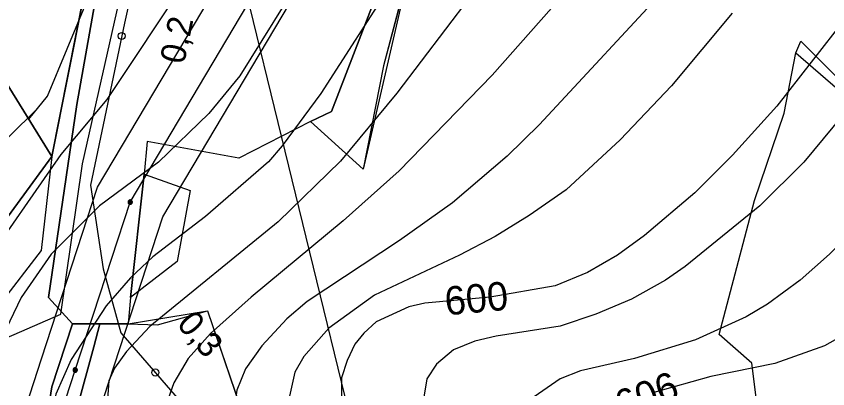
# Model space of a CAD drawing. Extents: x -709418 to -703832, y -1161719 to -1157826.
# Drawn here: x -706899.8 to -706671.8, y -1159381.5 to -1159276.9 of the extents above; entities that cross this region are included whole.
import ezdxf

# ---------------------------------------------------------------- set-up
doc = ezdxf.new("R2010")
doc.units = 0
for name, color, linetype in [('102_obvod PÚ', 7, 'Continuous'), ('106_zastavitelné plochy', 7, 'Continuous'), ('120_vrstevnice hlavní', 7, 'Continuous'), ('121_vrstevnice hlavní_popis', 7, 'Continuous'), ('122_vrstevnice základní', 7, 'Continuous'), ('206_TTP_KN', 7, 'Continuous'), ('207_lesní pozemek_KN', 7, 'Continuous'), ('210_ostatní plocha_KN', 7, 'Continuous'), ('301_polní cesta_stav', 7, 'Continuous'), ('705_el VN nadzemní_E.ON', 7, 'Continuous'), ('723_radioreléová trasa_UAP', 7, 'Continuous'), ('735_OP sítí TI', 7, 'Continuous'), ('Trasa-Hlavni  staniceni', 7, 'Continuous')]:
    doc.layers.add(name, color=color, linetype=linetype)

# ---------------------------------------------------------------- blocks, each defined once
blk = doc.blocks.new('Elektro - Implicitní$0$VN4601')
for points in [[(1.23, 0), (1.22, 0.13), (1.2, 0.26), (1.17, 0.38), (1.12, 0.5), (1.06, 0.61), (0.99, 0.72), (0.91, 0.82), (0.82, 0.91), (0.72, 0.99), (0.61, 1.06), (0.5, 1.12), (0.38, 1.17), (0.26, 1.2), (0.13, 1.22), (0, 1.23), (-0.13, 1.22), (-0.26, 1.2), (-0.38, 1.17), (-0.5, 1.12), (-0.61, 1.06), (-0.72, 0.99), (-0.82, 0.91), (-0.91, 0.82), (-0.99, 0.72), (-1.06, 0.61), (-1.12, 0.5), (-1.17, 0.38), (-1.2, 0.26), (-1.22, 0.13), (-1.23, 0), (-1.22, -0.13), (-1.2, -0.26), (-1.17, -0.38), (-1.12, -0.5), (-1.06, -0.61), (-0.99, -0.72), (-0.91, -0.82), (-0.82, -0.91), (-0.72, -0.99), (-0.61, -1.06), (-0.5, -1.12), (-0.38, -1.17), (-0.26, -1.2), (-0.13, -1.22), (0, -1.23), (0.13, -1.22), (0.26, -1.2), (0.38, -1.17), (0.5, -1.12), (0.61, -1.06), (0.72, -0.99), (0.82, -0.91), (0.91, -0.82), (0.99, -0.72), (1.06, -0.61), (1.12, -0.5), (1.17, -0.38), (1.2, -0.26), (1.22, -0.13), (1.23, 0)], [(0.92, 0), (0.92, 0.1), (0.9, 0.19), (0.88, 0.28), (0.84, 0.37), (0.8, 0.46), (0.75, 0.54), (0.68, 0.62), (0.62, 0.68), (0.54, 0.74), (0.46, 0.8), (0.37, 0.84), (0.28, 0.88), (0.19, 0.9), (0.1, 0.92), (0, 0.92), (-0.1, 0.92), (-0.19, 0.9), (-0.28, 0.88), (-0.37, 0.84), (-0.46, 0.8), (-0.54, 0.74), (-0.62, 0.68), (-0.68, 0.62), (-0.75, 0.54), (-0.8, 0.46), (-0.84, 0.37), (-0.88, 0.28), (-0.9, 0.19), (-0.92, 0.1), (-0.92, 0), (-0.92, -0.1), (-0.9, -0.19), (-0.88, -0.29), (-0.84, -0.38), (-0.8, -0.46), (-0.75, -0.54), (-0.68, -0.62), (-0.62, -0.69), (-0.54, -0.75), (-0.46, -0.8), (-0.37, -0.84), (-0.28, -0.88), (-0.19, -0.9), (-0.1, -0.92), (0, -0.92), (0.1, -0.92), (0.19, -0.9), (0.28, -0.88), (0.37, -0.84), (0.46, -0.8), (0.54, -0.75), (0.62, -0.69), (0.68, -0.62), (0.75, -0.54), (0.8, -0.46), (0.84, -0.38), (0.88, -0.29), (0.9, -0.19), (0.92, -0.1), (0.92, 0)], [(0.61, 0), (0.61, 0.06), (0.6, 0.13), (0.58, 0.19), (0.56, 0.25), (0.53, 0.31), (0.5, 0.36), (0.46, 0.41), (0.41, 0.46), (0.36, 0.5), (0.31, 0.53), (0.25, 0.56), (0.19, 0.58), (0.13, 0.6), (0.06, 0.61), (0, 0.61), (-0.06, 0.61), (-0.13, 0.6), (-0.19, 0.58), (-0.25, 0.56), (-0.31, 0.53), (-0.36, 0.5), (-0.41, 0.46), (-0.46, 0.41), (-0.5, 0.36), (-0.53, 0.31), (-0.56, 0.25), (-0.58, 0.19), (-0.6, 0.13), (-0.61, 0.06), (-0.61, 0), (-0.61, -0.07), (-0.6, -0.13), (-0.58, -0.19), (-0.56, -0.25), (-0.53, -0.31), (-0.5, -0.36), (-0.46, -0.41), (-0.41, -0.46), (-0.36, -0.5), (-0.31, -0.53), (-0.25, -0.56), (-0.19, -0.58), (-0.13, -0.6), (-0.06, -0.61), (0, -0.61), (0.06, -0.61), (0.13, -0.6), (0.19, -0.58), (0.25, -0.56), (0.31, -0.53), (0.36, -0.5), (0.41, -0.46), (0.46, -0.41), (0.5, -0.36), (0.53, -0.31), (0.56, -0.25), (0.58, -0.19), (0.6, -0.13), (0.61, -0.06), (0.61, 0)], [(0.31, 0), (0.31, 0.03), (0.3, 0.06), (0.29, 0.09), (0.28, 0.12), (0.27, 0.15), (0.25, 0.18), (0.23, 0.21), (0.21, 0.23), (0.18, 0.25), (0.15, 0.27), (0.12, 0.28), (0.09, 0.29), (0.06, 0.3), (0.03, 0.31), (0, 0.31), (-0.03, 0.31), (-0.06, 0.3), (-0.09, 0.29), (-0.12, 0.28), (-0.15, 0.27), (-0.18, 0.25), (-0.21, 0.23), (-0.23, 0.21), (-0.25, 0.18), (-0.27, 0.15), (-0.28, 0.12), (-0.29, 0.09), (-0.3, 0.06), (-0.31, 0.03), (-0.31, 0), (-0.31, -0.03), (-0.3, -0.06), (-0.29, -0.1), (-0.28, -0.13), (-0.27, -0.15), (-0.25, -0.18), (-0.23, -0.21), (-0.21, -0.23), (-0.18, -0.25), (-0.15, -0.27), (-0.12, -0.28), (-0.09, -0.29), (-0.06, -0.3), (-0.03, -0.31), (0, -0.31), (0.03, -0.31), (0.06, -0.3), (0.09, -0.29), (0.12, -0.28), (0.15, -0.27), (0.18, -0.25), (0.21, -0.23), (0.23, -0.21), (0.25, -0.18), (0.27, -0.15), (0.28, -0.13), (0.29, -0.1), (0.3, -0.06), (0.31, -0.03), (0.31, 0)]]:
    blk.add_lwpolyline(points)
blk = doc.blocks.new('_kolecko-HB')
blk.add_circle((0, 0), 0.5)

msp = doc.modelspace()

# ---------------------------------------------------------------- linework, layer by layer
at = {"layer": '102_obvod PÚ'}
for points in [[(-706968.04, -1159233.11), (-706937.28, -1159184.2), (-706914.8, -1159202.04), (-706906.78, -1159204.53), (-706877.16, -1159210.67), (-706869.31, -1159212.81), (-706889.81, -1159316.26), (-706920.66, -1159266.5), (-706951.63, -1159256.73), (-706968.04, -1159233.11)], [(-706968.04, -1159233.11), (-706951.63, -1159256.73), (-706920.66, -1159266.5), (-706889.81, -1159316.26), (-706869.31, -1159212.81), (-706877.16, -1159210.67), (-706906.78, -1159204.53), (-706914.8, -1159202.04), (-706937.28, -1159184.2), (-706968.04, -1159233.11)], [(-706788.31, -1159259.5), (-706796.68, -1159290.77), (-706802.33, -1159319.86), (-706817.16, -1159306.4), (-706837.26, -1159316.76), (-706863.04, -1159312.08), (-706863.88, -1159321.25), (-706850.99, -1159325.84), (-706854.62, -1159345.77), (-706867.73, -1159355.84), (-706868.36, -1159363.26), (-706860.13, -1159363.56), (-706846.05, -1159359.62), (-706835.89, -1159389.45)], [(-706689.26, -1159404.94), (-706693.14, -1159374.31), (-706702.27, -1159366.26), (-706692.33, -1159328.63), (-706684.03, -1159304.11), (-706680.78, -1159287.17), (-706679.32, -1159283.86), (-706646.77, -1159316.53)]]:
    msp.add_lwpolyline(points, dxfattribs=at)
at = {"layer": '106_zastavitelné plochy'}
for points in [[(-706867.98, -1159123.82), (-706903.51, -1159148.06), (-706940.53, -1159172.06), (-706937.28, -1159184.2), (-706968.04, -1159233.11), (-706951.63, -1159256.73), (-706920.66, -1159266.5), (-706889.81, -1159316.26), (-706892.83, -1159342.7), (-706904.42, -1159357.69), (-706932.38, -1159369.27), (-706950.1, -1159377.45), (-706984.19, -1159324.98), (-706993.05, -1159311.35), (-707005.32, -1159252.75), (-706918.72, -1159056.21)], [(-706984.14, -1159571.11), (-706940.51, -1159526.82), (-706927.56, -1159471.62), (-706911.88, -1159458.67), (-706913.24, -1159422.56), (-706940.51, -1159383.71), (-706887.33, -1159360.55), (-706881.2, -1159318.3), (-706858.02, -1159215.4), (-706843.02, -1159201.77), (-706814.39, -1159228.35), (-706755.76, -1159179.96), (-706722.35, -1159147.93), (-706588.73, -1159106.37)], [(-706780.18, -1159223.54), (-706802.33, -1159319.86), (-706817.16, -1159306.4), (-706837.26, -1159316.76), (-706863.04, -1159312.08), (-706863.88, -1159321.25), (-706850.99, -1159325.84), (-706854.62, -1159345.77), (-706867.73, -1159355.84), (-706868.36, -1159363.26), (-706846.05, -1159359.62), (-706835.89, -1159389.45), (-706819.69, -1159405.02), (-706830.93, -1159469.93), (-706862.53, -1159500.28), (-706880.78, -1159493.2), (-706892.53, -1159517.73), (-706883.24, -1159539.08), (-706874.38, -1159567.71)], [(-706813.66, -1159590.44), (-706782.3, -1159546.83), (-706735.26, -1159468.47), (-706721.2, -1159414.52), (-706695.54, -1159419.88), (-706689.26, -1159404.94), (-706693.14, -1159374.31), (-706702.27, -1159366.26), (-706692.33, -1159328.63), (-706684.03, -1159304.11), (-706680.78, -1159287.17), (-706646.77, -1159316.53), (-706635.13, -1159349.04), (-706595.43, -1159358.62), (-706601.6, -1159380.41), (-706622.05, -1159413.8), (-706651.36, -1159436.97), (-706699.08, -1159526.92), (-706830.66, -1159663.21)]]:
    msp.add_lwpolyline(points, dxfattribs=at)
at = {"layer": '120_vrstevnice hlavní'}
for points in [[(-706794.12, -1159267.17), (-706814.27, -1159298.6), (-706825.12, -1159313.32), (-706828.98, -1159317.74), (-706846.7, -1159333.17), (-706861.41, -1159344.46), (-706867.7, -1159350.32), (-706874.56, -1159358.18), (-706884.41, -1159373.32), (-706888.7, -1159383.03), (-706889.7, -1159387.89), (-706889.84, -1159392.75), (-706889.13, -1159397.6), (-706887.56, -1159402.46), (-706882.41, -1159412.18), (-706879.41, -1159421.89), (-706879.41, -1159426.75), (-706880.27, -1159431.61), (-706882.13, -1159436.46), (-706884.84, -1159441.32), (-706891.41, -1159450.89), (-706904.56, -1159460.32)], [(-706666.83, -1159277.46), (-706686.12, -1159302.17), (-706698.55, -1159315.89), (-706709.12, -1159326.46), (-706723.26, -1159338.46), (-706730.84, -1159344.03), (-706739.26, -1159348.89), (-706748.41, -1159352.6), (-706766.69, -1159355.75), (-706784.98, -1159357.46), (-706789.55, -1159358.46), (-706798.7, -1159362.75), (-706802.12, -1159365.89), (-706804.7, -1159369.03), (-706806.84, -1159373.6), (-706808.41, -1159378.46), (-706808.41, -1159383.32), (-706807.55, -1159388.18), (-706805.84, -1159393.03), (-706800.7, -1159402.75), (-706785.7, -1159424.18), (-706783.27, -1159429.04), (-706780.12, -1159439.75)]]:
    msp.add_lwpolyline(points, dxfattribs=at)
at = {"layer": '122_vrstevnice základní'}
for points in [[(-706896.34, -1159305.76), (-706891.06, -1159299.33), (-706868.97, -1159246.1), (-706862.43, -1159234.32), (-706837.41, -1159204.45), (-706811.55, -1159175.45), (-706794.98, -1159159.17), (-706778.12, -1159144.59), (-706752.98, -1159125.88), (-706702.69, -1159085.59), (-706687.55, -1159074.88), (-706663.69, -1159061.59), (-706650.83, -1159056.16), (-706631.55, -1159049.87), (-706622.97, -1159047.87), (-706605.83, -1159045.3), (-706569.16, -1159041.88)], [(-706691.92, -1159113.47), (-706717.27, -1159130.62), (-706738.69, -1159144.59), (-706771.98, -1159173.74), (-706783.41, -1159184.45), (-706792.55, -1159194.02), (-706827.55, -1159235.03), (-706840.84, -1159251.6), (-706851.98, -1159266.6), (-706874.41, -1159300.31), (-706887.27, -1159315.74)], [(-706677.1, -1159123.23), (-706695.83, -1159135.45), (-706715.69, -1159150.17), (-706735.69, -1159167.74), (-706763.69, -1159195.45), (-706783.7, -1159217.45), (-706805.84, -1159244.6), (-706817.98, -1159263.03), (-706836.98, -1159293.6), (-706845.7, -1159304.17), (-706859.84, -1159317.89), (-706876.41, -1159330.17), (-706889.99, -1159343.75), (-706898.42, -1159355.89), (-706903.84, -1159367.03), (-706906.27, -1159374.75), (-706908.27, -1159387.6), (-706908.42, -1159392.75), (-706907.7, -1159400.6)], [(-706651.26, -1159189.31), (-706674.4, -1159215.17), (-706689.69, -1159233.74), (-706698.83, -1159246.31), (-706715.26, -1159266.74), (-706752.84, -1159307.31), (-706761.84, -1159316.17), (-706777.27, -1159329.32), (-706792.12, -1159339.89), (-706818.12, -1159357.03), (-706823.84, -1159361.89), (-706830.84, -1159369.46), (-706835.41, -1159375.89), (-706837.84, -1159381.89), (-706838.98, -1159389.89), (-706838.56, -1159393.75), (-706835.41, -1159401.03), (-706824.55, -1159417.04), (-706812.55, -1159438.04), (-706812.7, -1159445.61), (-706815.84, -1159451.18), (-706820.41, -1159455.89), (-706843.94, -1159481.51)], [(-706590.33, -1159211.59), (-706594.67, -1159221.73), (-706609.26, -1159257.6), (-706614.97, -1159269.6), (-706620.54, -1159279.31), (-706635.83, -1159302.6), (-706648.12, -1159318.17), (-706662.55, -1159335.03), (-706671.26, -1159343.75), (-706679.55, -1159351.03), (-706688.69, -1159357.75), (-706694.69, -1159361.32), (-706708.98, -1159367.75), (-706726.12, -1159373.03), (-706741.26, -1159376.46), (-706746.98, -1159378.75), (-706754.27, -1159383.75), (-706758.41, -1159388.32), (-706761.12, -1159393.32), (-706761.12, -1159398.46), (-706758.27, -1159408.46), (-706754.12, -1159416.46), (-706746.27, -1159438.04)], [(-706708.83, -1159228.74), (-706766.12, -1159293.46), (-706792.27, -1159320.32), (-706807.98, -1159334.32), (-706833.84, -1159355.75), (-706845.27, -1159366.03), (-706851.56, -1159373.03), (-706855.56, -1159379.89), (-706857.7, -1159385.89)], [(-706751.84, -1159244.46), (-706792.84, -1159298.46), (-706808.7, -1159317.6), (-706826.27, -1159334.6), (-706862.27, -1159364.03), (-706868.84, -1159371.03), (-706872.27, -1159375.75), (-706873.84, -1159379.32), (-706874.41, -1159387.03), (-706871.98, -1159397.03), (-706864.13, -1159417.04), (-706861.7, -1159427.04), (-706860.98, -1159433.04), (-706861.7, -1159443.04), (-706863.84, -1159449.04), (-706867.41, -1159454.75), (-706877.41, -1159465.18), (-706913.56, -1159493.61), (-706937.13, -1159519.18), (-706948.54, -1159535.57), (-706952.12, -1159541.68), (-706957.97, -1159552.45)], [(-706698.69, -1159276.03), (-706715.69, -1159296.46), (-706730.12, -1159311.6), (-706745.26, -1159325.6), (-706755.69, -1159332.89), (-706765.27, -1159338.75), (-706775.27, -1159344.03), (-706799.12, -1159355.18), (-706811.98, -1159364.46), (-706818.98, -1159372.46), (-706821.55, -1159376.89), (-706823.27, -1159384.46)], [(-706657.26, -1159292.17), (-706678.55, -1159317.89), (-706690.83, -1159330.17), (-706711.83, -1159347.17), (-706717.41, -1159351.03), (-706726.98, -1159356.32), (-706736.98, -1159360.6), (-706746.98, -1159363.89), (-706764.98, -1159366.75), (-706770.98, -1159368.18), (-706776.98, -1159370.6), (-706781.7, -1159374.6), (-706784.41, -1159378.75), (-706785.55, -1159385.6)], [(-706893.89, -1159302.78), (-706909.99, -1159318.6), (-706913.84, -1159323.03), (-706918.99, -1159330.46), (-706926.42, -1159343.89), (-706934.85, -1159365.6), (-706935.85, -1159377.03), (-706935.85, -1159393.03), (-706938.85, -1159406.75), (-706942.99, -1159415.89), (-706950.56, -1159427.61), (-706973.42, -1159455.75), (-706984.06, -1159473.45), (-706988.15, -1159481.26), (-707000.79, -1159480.88), (-707010.28, -1159499.04), (-707018.97, -1159515.02), (-707035.98, -1159542.9)], [(-706887.27, -1159315.74), (-706910.13, -1159348.46), (-706917.99, -1159364.46), (-706921.56, -1159374.75), (-706925.85, -1159397.89), (-706927.56, -1159418.46), (-706929.56, -1159426.18), (-706931.85, -1159431.32), (-706937.42, -1159439.46), (-706944.85, -1159447.89), (-706969.56, -1159472.61), (-706976.7, -1159481.18), (-706982.42, -1159490.18), (-706989.99, -1159505.61), (-706993.35, -1159523.55), (-706991.59, -1159547.07), (-706991.85, -1159548.26)], [(-706660.69, -1159362.75), (-706672.69, -1159369.46), (-706686.69, -1159374.46), (-706704.69, -1159378.03), (-706720.69, -1159382.6)]]:
    msp.add_lwpolyline(points, dxfattribs=at)
at = {"layer": '206_TTP_KN'}
for p, q in [((-706780.18, -1159223.54), (-706811.28, -1159303.59)), ((-706811.28, -1159303.59), (-706780.18, -1159223.54)), ((-706882.85, -1159301.66), (-706871.87, -1159239.91)), ((-706788.31, -1159259.5), (-706796.68, -1159290.77)), ((-706796.68, -1159290.77), (-706802.33, -1159319.86)), ((-706890.77, -1159355.9), (-706882.85, -1159301.66)), ((-706811.28, -1159303.59), (-706817.16, -1159306.4)), ((-706817.16, -1159306.4), (-706811.28, -1159303.59)), ((-706817.16, -1159306.4), (-706837.26, -1159316.76)), ((-706802.33, -1159319.86), (-706817.16, -1159306.4)), ((-706863.04, -1159312.08), (-706863.88, -1159321.25)), ((-706837.26, -1159316.76), (-706863.04, -1159312.08)), ((-706863.88, -1159321.25), (-706867.73, -1159355.84)), ((-706867.73, -1159355.84), (-706863.88, -1159321.25)), ((-706863.88, -1159321.25), (-706850.99, -1159325.84)), ((-706850.99, -1159325.84), (-706854.62, -1159345.77)), ((-706854.62, -1159345.77), (-706867.73, -1159355.84)), ((-706883.99, -1159363.25), (-706890.77, -1159355.9)), ((-706867.73, -1159355.84), (-706868.36, -1159363.26)), ((-706860.13, -1159363.56), (-706846.05, -1159359.62)), ((-706846.05, -1159359.62), (-706835.89, -1159389.45)), ((-706876.31, -1159363.29), (-706883.99, -1159363.25)), ((-706878.05, -1159369.69), (-706876.31, -1159363.29)), ((-706876.31, -1159363.29), (-706868.36, -1159363.26)), ((-706868.36, -1159363.26), (-706876.31, -1159363.29)), ((-706868.36, -1159363.26), (-706860.13, -1159363.56)), ((-706892.19, -1159421.53), (-706878.05, -1159369.69))]:
    msp.add_line(p, q, dxfattribs=at)
for points in [[(-707008.91, -1159258.29), (-707008.55, -1159251.22), (-706982.76, -1159187.68), (-706961.99, -1159166.3), (-706937.28, -1159184.2), (-706968.04, -1159233.11), (-706951.63, -1159256.73), (-706920.66, -1159266.5), (-706889.81, -1159316.26), (-706904.9, -1159336.81), (-706919.94, -1159353.31), (-706945.24, -1159369.3), (-706983.84, -1159296.79), (-707001.13, -1159299.78), (-707003.84, -1159287.15), (-707007.41, -1159269.1), (-707008.91, -1159258.29)], [(-706811.57, -1159580.5), (-706787.66, -1159545.74), (-706772.75, -1159524.48), (-706755.69, -1159496.43), (-706739.99, -1159464.75), (-706731.65, -1159434.49), (-706729.3, -1159428.78), (-706721.2, -1159414.52), (-706695.54, -1159419.88), (-706689.26, -1159404.94), (-706693.14, -1159374.31), (-706702.27, -1159366.26), (-706692.33, -1159328.63), (-706684.03, -1159304.11), (-706680.78, -1159287.17), (-706679.32, -1159283.86), (-706646.77, -1159316.53)]]:
    msp.add_lwpolyline(points, dxfattribs=at)
at = {"layer": '207_lesní pozemek_KN'}
for p, q in [((-706869.31, -1159212.81), (-706889.81, -1159316.26)), ((-706889.81, -1159316.26), (-706920.66, -1159266.5))]:
    msp.add_line(p, q, dxfattribs=at)
at = {"layer": '210_ostatní plocha_KN'}
for p, q in [((-706889.81, -1159316.26), (-706869.31, -1159212.81)), ((-706871.87, -1159239.91), (-706882.85, -1159301.66)), ((-706882.85, -1159301.66), (-706890.77, -1159355.9)), ((-706904.9, -1159336.81), (-706889.81, -1159316.26)), ((-706890.77, -1159355.9), (-706883.99, -1159363.25)), ((-706889.8, -1159380.99), (-706883.99, -1159363.25)), ((-706883.99, -1159363.25), (-706889.8, -1159380.99)), ((-706883.99, -1159363.25), (-706876.31, -1159363.29)), ((-706876.31, -1159363.29), (-706878.05, -1159369.69)), ((-706878.05, -1159369.69), (-706892.19, -1159421.53)), ((-706894.51, -1159407.96), (-706889.8, -1159380.99)), ((-706889.8, -1159380.99), (-706894.51, -1159407.96))]:
    msp.add_line(p, q, dxfattribs=at)
at = {"layer": '301_polní cesta_stav'}
msp.add_lwpolyline([(-706895.45, -1159195.94), (-706868.46, -1159206.93), (-706857.47, -1159224.91), (-706869.46, -1159278.85), (-706878.96, -1159324.3), (-706875.46, -1159347.78), (-706870.46, -1159365.76), (-706847.97, -1159391.73), (-706812.48, -1159430.69), (-706794.49, -1159445.68), (-706755.51, -1159444.18), (-706735.52, -1159437.18), (-706723.52, -1159439.68), (-706700.03, -1159452.67), (-706662.55, -1159471.15)], dxfattribs=at)
at = {"layer": '705_el VN nadzemní_E.ON'}
msp.add_lwpolyline([(-706880.73, -1160218.11), (-706883.24, -1160121.67), (-706885.97, -1160030.15), (-706888.81, -1159867.66), (-706890.66, -1159770.11), (-706893.19, -1159670.63), (-706895.78, -1159542.24), (-706897.96, -1159421.41), (-706883.28, -1159376.25), (-706867.82, -1159329.09), (-706796.05, -1159208.33), (-706732.4, -1159102.13), (-706682.71, -1159018.58)], dxfattribs=at)
at = {"layer": '723_radioreléová trasa_UAP'}
msp.add_lwpolyline([(-707182.2, -1157850.62), (-706271.36, -1161577.76)], dxfattribs=at)
at = {"layer": '735_OP sítí TI'}
for points in [[(-706890.9, -1160211.71), (-706893.24, -1160121.95), (-706895.97, -1160030.39), (-706898.81, -1159867.84), (-706900.66, -1159770.33), (-706903.19, -1159670.86), (-706905.78, -1159542.43), (-706907.99, -1159419.91), (-706892.79, -1159373.15), (-706876.98, -1159324.93), (-706804.64, -1159203.21), (-706740.99, -1159097), (-706691.31, -1159013.46)], [(-706870.8, -1160215.44), (-706873.24, -1160121.39), (-706875.97, -1160029.91), (-706878.81, -1159867.48), (-706880.66, -1159769.89), (-706883.19, -1159670.4), (-706885.78, -1159542.05), (-706887.93, -1159422.91), (-706873.77, -1159379.35), (-706858.66, -1159333.25), (-706787.46, -1159213.45), (-706723.81, -1159107.26), (-706674.12, -1159023.69)]]:
    msp.add_lwpolyline(points, dxfattribs=at)

# ---------------------------------------------------------------- block references
at = {"layer": '705_el VN nadzemní_E.ON', "xscale": 0.5, "yscale": 0.5}
for p, rotation in [((-706867.82, -1159329.09), 60.361261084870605), ((-706883.28, -1159376.25), 60.36126121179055)]:
    msp.add_blockref('Elektro - Implicitní$0$VN4601', p, dxfattribs=dict(at, rotation=rotation))
at = {"layer": 'Trasa-Hlavni  staniceni', "xscale": 1.999999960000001}
for p, yscale, rotation in [((-706870.2, -1159282.42), 1.999999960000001, -101.80055898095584), ((-706860.76, -1159376.96), 1.9999999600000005, -49.1098897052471)]:
    msp.add_blockref('_kolecko-HB', p, dxfattribs=dict(at, yscale=yscale, rotation=rotation))

# ---------------------------------------------------------------- texts
at = {"layer": '121_vrstevnice hlavní_popis'}
for s, rotation, p in [('600', 5.3034, (-706779.07, -1159360.92)), ('606', 20.8343, (-706729.65, -1159390.2))]:
    msp.add_text(s, height=8, rotation=rotation, dxfattribs=at).set_placement(p)
at = {"layer": 'Trasa-Hlavni  staniceni'}
for s, rotation, p in [('0,2', 78.1994, (-706852.68, -1159290.57)), ('0,3', 310.8901, (-706855, -1159363.47))]:
    msp.add_text(s, height=7, rotation=rotation, dxfattribs=at).set_placement(p)

doc.saveas('drawing.dxf')
